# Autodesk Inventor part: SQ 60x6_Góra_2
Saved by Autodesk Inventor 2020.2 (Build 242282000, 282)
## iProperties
Created: 2006-08
Part Number: SQ 60x6_Góra_2
Material: Ogólny
Document SubType Name: Modeling
Designer: F.Stasiak
Manufacturer: Standard
Standards Organization: Custom
Stock Number: DIN EN 10210-2 SQ 60x6
Density: 1 g/cm^3
Appearance: Domyślna
Manager: www.cadconsulting.pl
Company: Fabian Stasiak CAD Consulting
G_L: 1000,0 mm
G_W: 60,000 mm
G_H: 60,000 mm
AFG_Item: 60 x 60 x 6
Author: F.Stasiak
Subject: Zbiór ćwiczeń. Autodesk Inventor 2020. Kurs podstawowy
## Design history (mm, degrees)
sketch "AFG_Detailed"
  geometry: L1 (48, 54)-(12, 54); L2 (6, 48)-(6, 12); L3 (12, 6)-(48, 6); L4 (54, 12)-(54, 48); L5 (48, 60)-(12, 60); L6 (0, 48)-(0, 12); L7 (12, 0)-(48, 0); L8 (60, 12)-(60, 48); A1 r 6 centre (48, 48) between (54, 48) and (48, 54); A2 r 12 centre (48, 48) between (60, 48) and (48, 60); A3 r 6 centre (48, 12) between (48, 6) and (54, 12); A4 r 12 centre (48, 12) between (48, 0) and (60, 12); A5 r 12 centre (12, 12) between (0, 12) and (12, 0); A6 r 6 centre (12, 12) between (6, 12) and (12, 6); A7 r 6 centre (12, 48) between (12, 54) and (6, 48); A8 r 12 centre (12, 48) between (12, 60) and (0, 48); 4 further points
  constraints: 16 end point, 16 point on circle, 16 tangent, 8 centre point, 6 point on line, 4 parallel, 2 perpendicular, 1 vertical
  dimensions: "d15" = 60 distance of point (0, 0) point (60, 0) (= GEO_B); "d16" = 6 distance between parallel lines of L7 L3 (= GEO_S); "d17" = 6 distance between parallel lines of L8 L4 (= GEO_S); "d18" = 6 distance between parallel lines of L5 L1 (= GEO_S); "d19" = 6 distance between parallel lines of L6 L2 (= GEO_S); "d20" = 30 distance from line of point (30, 30) L7 (= 0.5 x GEO_H); "d30" = 6 radius of A1 (= GEO_R1 - GEO_S); "GEO_R1" = 12 radius of A2; "d32" = 6 radius of A3 (= GEO_R1 - GEO_S); "d33" = 12 radius of A4 (= GEO_R1); "d34" = 12 radius of A5 (= GEO_R1); "d35" = 6 radius of A6 (= GEO_R1 - GEO_S); "d36" = 6 radius of A7 (= GEO_R1 - GEO_S); "d37" = 12 radius of A8 (= GEO_R1); "d38" = 30 distance from line of L6 point (30, 30) (= 0.5 x GEO_B); "d39" = 60 distance between parallel lines of L7 L5 (= GEO_H)
sketch "AFG_Medium"
  geometry: L1 (54, 54)-(6, 54); L2 (6, 54)-(6, 6); L3 (6, 6)-(54, 6); L4 (54, 6)-(54, 54); L5 (60, 60)-(0, 60); L6 (0, 60)-(0, 0); L7 (0, 0)-(60, 0); L8 (60, 0)-(60, 60); 1 further point
  constraints: 16 end point, 4 parallel, 2 perpendicular, 1 vertical
  dimensions: "GEO_B" = 60 distance of L6.end L7.end; "GEO_S" = 6 distance between parallel lines of L7 L3; "d5" = 6 distance between parallel lines of L8 L4 (= GEO_S); "d6" = 6 distance between parallel lines of L5 L1 (= GEO_S); "d7" = 6 distance between parallel lines of L6 L2 (= GEO_S); "d12" = 30 distance from line of point (30, 30) L7 (= 0.5 x GEO_H); "d40" = 60 distance between parallel lines of L7 L5 (= GEO_H); "d41" = 30 distance from line of L6 point (30, 30) (= 0.5 x GEO_B)
sketch "AFG_Simplified"
  geometry: L1 (60, 60)-(0, 60); L2 (0, 60)-(0, 0); L3 (0, 0)-(60, 0); L4 (60, 0)-(60, 60); 1 further point
  constraints: 8 end point, 2 parallel, 1 perpendicular, 1 vertical
  dimensions: "d23" = 60 distance of L2.end L3.end (= GEO_B); "d28" = 30 distance from line of point (30, 30) L3 (= 0.5 x GEO_H); "d42" = 60 distance between parallel lines of L3 L1 (= GEO_H); "d43" = 30 distance from line of point (30, 30) L2 (= 0.5 x GEO_B)
derived "Szkielet podstawy.ipt"
  sketch "Szkic1"
    geometry: L1 (0, 0)-(1500, 0) reference; L2 (1500, 0)-(1500, 1000) reference; L3 (1500, 1000)-(0, 1000) reference; L4 (0, 1000)-(0, 0) reference
  sketch "Szkic2"
    geometry: L1 (0, 1000)-(0, 0) reference; L2 (0, 0)-(1500, 0) reference; L3 (1500, 0)-(1500, 1000) reference; L4 (500, 1000)-(1500, 1000) reference; L5 (1500, 1000)-(1500, 0) reference; L6 (1500, 0)-(500, 0) reference; L7 (500, 0)-(500, 1000) reference; L8 (1500, 1000)-(0, 1000) reference
node "AFG_StartWorkPoint_SQ 60x6_Góra_2"
node "AFG_EndWorkPoint_SQ 60x6_Góra_2"
node "AFG_HelpAxis"
node "AFG_HelpStart"
node "AFG_HelpEnd"
node "AFG_Midplane"
  node "AFG_Startplane"
  node "AFG_EndPlane"
node "AFG_Profile_AxisX_for_External_Matrix"
extrude "AFG_Detailed_SQ 60x6_Góra_2" join sketch "AFG_Detailed" stored distance "d49" = 0.13; taper "d50" = 0 deg
extrude "AFG_Simplified_SQ 60x6_Góra_2" join sketch "AFG_Simplified" stored distance "d51" = 0.13; taper "d52" = 0 deg
node "AFG_StartWorkPoint_SQ 60x6_Góra_3"
node "AFG_EndWorkPoint_SQ 60x6_Góra_3"
node "AFG_ENDCUTPLANE_SQ 60x6_Góra_2"
node "AFG_StartWorkPoint_SQ 60x6_Góra_1"
node "AFG_EndWorkPoint_SQ 60x6_Góra_1"
node "AFG_STARTCUTPLANE_SQ 60x6_Góra_2"
node "Bryła1"
node "Korpusy bryłowe"
node "Korpusy powierzchniowe"
other parameters: "GEO_H" = 60, "AFG_Origin_X" = 0 (= 0 x GEO_B) [user parameter], "AFG_Origin_Y" = 0 (= 0 x GEO_H) [user parameter], "AFG_IP_X2" = 0 (= 0 x GEO_B) [user parameter], "AFG_IP_Y4" = 0 (= 0 x GEO_H) [user parameter], "AFG_IP_X6" = 0 (= 0 x GEO_B) [user parameter], "AFG_IP_Y8" = 0 (= 0 x GEO_H) [user parameter], "d47" = 0, "d48" = 0, "G_L" = 1000 [user parameter], "d55" = 0, "d58" = 0
